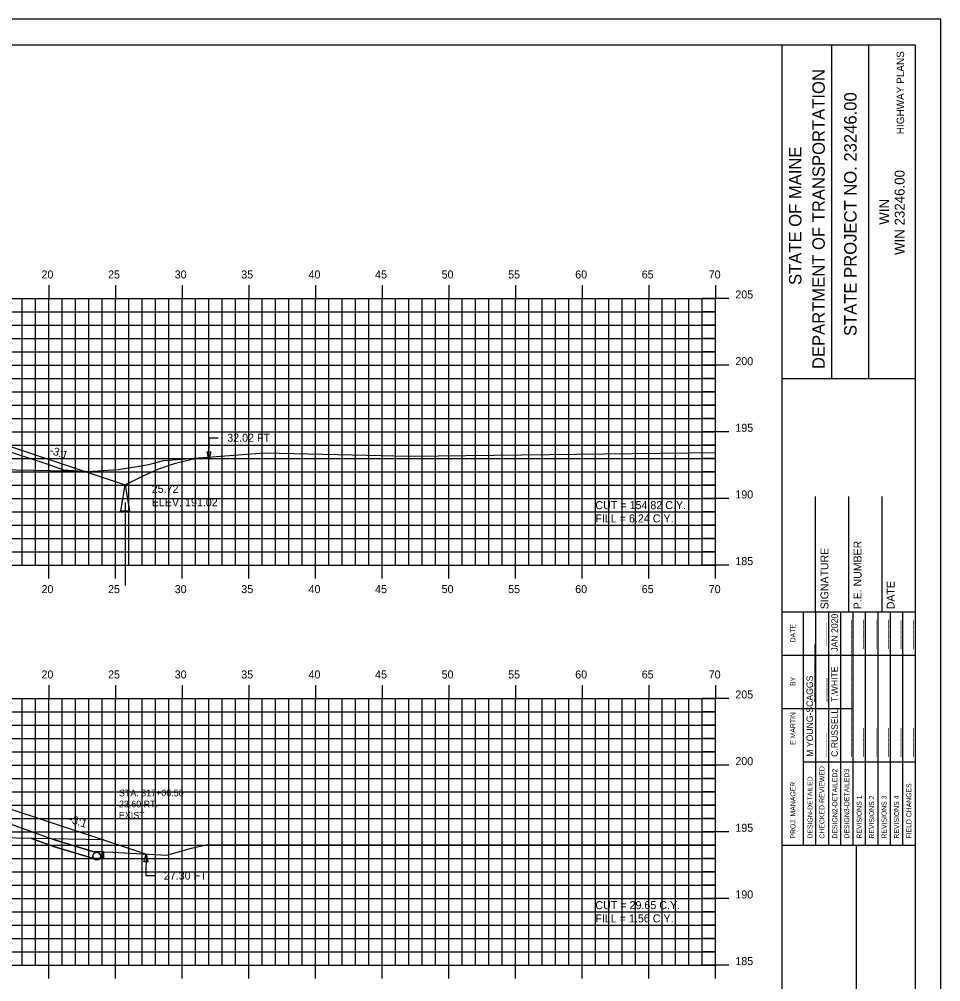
# Model space of a CAD drawing. Extents: x 1138985 to 1139155, y 608981 to 609091.
# Drawn here: x 1139085.7 to 1139154.9, y 609019.1 to 609091.3 of the extents above; entities that cross this region are included whole.
import ezdxf

# ---------------------------------------------------------------- set-up
doc = ezdxf.new("R2010")
doc.units = 0
for name, color, linetype in [('ANNOTATION', 7, 'Continuous'), ('BORDER', 7, 'Continuous'), ('D_Drainage_Ditch_Line', 7, 'Continuous'), ('D_Roadway_SlopeLines', 7, 'Continuous'), ('D_Roadway_SubGrade', 7, 'Continuous'), ('D_Text_Monospaced', 7, 'Continuous'), ('D_Text_Standard', 7, 'Continuous'), ('H_V ANNOTATION', 7, 'Continuous'), ('HIGHWAY_TITLE', 7, 'Continuous'), ('MAJOR', 7, 'Continuous'), ('MINOR', 7, 'Continuous'), ('PLOT BOUNDARY', 7, 'Continuous'), ('S_Drainage_Invert', 7, 'Continuous'), ('S_Roadway_Centerline', 7, 'Continuous'), ('SHADING', 7, 'Continuous')]:
    doc.layers.add(name, color=color, linetype=linetype)

msp = doc.modelspace()

# ---------------------------------------------------------------- linework, layer by layer
for points in [[(1139032.911, 609059.91), (1139051.198, 609059.859), (1139051.199, 609059.859), (1139051.403, 609060.487), (1139051.699, 609060.499), (1139051.949, 609059.889), (1139056.949, 609060.089), (1139067.949, 609060.309), (1139078.949, 609060.089), (1139082.949, 609059.929), (1139090.672, 609057.354), (1139093.672, 609056.354), (1139094.967, 609057.001), (1139096.217, 609057.56), (1139097.467, 609057.986), (1139098.717, 609058.28), (1139099.967, 609058.441)], [(1139037.654, 609031.141), (1139051.949, 609032.284), (1139056.949, 609032.484), (1139067.949, 609032.704), (1139078.949, 609032.484), (1139084.428, 609032.265), (1139092.057, 609029.722), (1139095.057, 609028.722), (1139095.244, 609028.66)]]:
    msp.add_lwpolyline(points)
at = {"layer": 'BORDER'}
for p, q in [((1139142.949, 608984.335), (1139142.949, 609089.335)), ((1139146.677, 609064.332), (1139146.677, 609089.332)), ((1139149.473, 609064.332), (1139149.473, 609089.332)), ((1139142.95, 609064.329), (1139152.949, 609064.329)), ((1139145.449, 609046.838), (1139145.449, 609055.485)), ((1139147.949, 609046.838), (1139147.949, 609055.485)), ((1139150.449, 609046.838), (1139150.449, 609055.485)), ((1139142.949, 609046.838), (1139152.949, 609046.838)), ((1139142.949, 609029.338), (1139152.949, 609029.338)), ((1139148.54, 608994.338), (1139148.54, 609029.338))]:
    msp.add_line(p, q, dxfattribs=at)
msp.add_lwpolyline([(1138992.949, 608984.335), (1139152.949, 608984.335), (1139152.949, 609089.335), (1138992.949, 609089.335)], close=True, dxfattribs=at)
for points in [[(1139144.564, 609043.588), (1139144.564, 609046.838)], [(1139145.496, 609029.341), (1139145.496, 609046.838)], [(1139146.428, 609046.838), (1139146.428, 609029.341)], [(1139147.36, 609029.341), (1139147.36, 609046.838)], [(1139148.291, 609029.341), (1139148.291, 609046.838)], [(1139149.223, 609029.341), (1139149.223, 609046.838)], [(1139150.155, 609029.341), (1139150.155, 609046.838)], [(1139151.086, 609029.341), (1139151.086, 609046.838)], [(1139152.018, 609029.341), (1139152.018, 609046.838)], [(1139144.565, 609029.341), (1139144.565, 609046.132)], [(1139142.949, 609043.588), (1139152.949, 609043.588)], [(1139142.949, 609039.588), (1139144.565, 609039.588)], [(1139144.564, 609039.588), (1139148.29, 609039.588)], [(1139144.564, 609035.588), (1139152.949, 609035.588)]]:
    msp.add_lwpolyline(points, dxfattribs=at)
at = {"layer": 'D_Drainage_Ditch_Line'}
msp.add_line((1139093.672, 609055.042), (1139093.672, 609048.798), dxfattribs=at)
msp.add_lwpolyline([(1139094, 609054.386), (1139093.344, 609054.386), (1139093.672, 609056.354)], close=True, dxfattribs=at)
at = {"layer": 'D_Roadway_SlopeLines'}
for points in [[(1139093.672, 609056.354), (1139094.967, 609057.001), (1139096.217, 609057.56), (1139097.467, 609057.986), (1139098.717, 609058.28), (1139099.967, 609058.441)], [(1139090.672, 609057.354), (1139093.672, 609056.354)], [(1139092.057, 609028.828), (1139092.057, 609028.328), (1139091.238, 609028.362), (1139088.304, 609029.233), (1139086.66, 609029.83)], [(1139092.057, 609029.722), (1139095.057, 609028.722)], [(1139095.057, 609028.722), (1139095.244, 609028.66)]]:
    msp.add_lwpolyline(points, dxfattribs=at)
at = {"layer": 'D_Roadway_SubGrade'}
for points in [[(1139078.949, 609059.672), (1139078.949, 609059.839), (1139082.949, 609059.679), (1139082.949, 609059.929), (1139082.949, 609059.929), (1139090.672, 609057.354), (1139078.949, 609057.589)], [(1139078.949, 609032.068), (1139078.949, 609032.234), (1139084.428, 609032.015), (1139084.428, 609032.265), (1139084.428, 609032.265), (1139092.057, 609029.722), (1139078.949, 609029.984)]]:
    msp.add_lwpolyline(points, close=True, dxfattribs=at)
at = {"layer": 'D_Text_Standard'}
for points in [[(1139099.967, 609058.251), (1139099.974, 609059.889), (1139100.654, 609059.889)], [(1139095.244, 609028.66), (1139095.22, 609027.049), (1139095.9, 609027.049)]]:
    msp.add_lwpolyline(points, dxfattribs=at)
for points in [[(1139099.967, 609058.251), (1139099.824, 609058.834), (1139100.115, 609058.833)], [(1139095.244, 609028.66), (1139095.381, 609028.076), (1139095.09, 609028.08)]]:
    msp.add_lwpolyline(points, close=True, dxfattribs=at)
at = {"layer": 'MAJOR'}
for p, q in [((1139087.949, 609071.337), (1139087.949, 609070.335)), ((1139092.949, 609071.337), (1139092.949, 609070.335)), ((1139097.949, 609071.337), (1139097.949, 609070.335)), ((1139102.949, 609071.337), (1139102.949, 609070.335)), ((1139107.949, 609071.337), (1139107.949, 609070.335)), ((1139112.949, 609071.337), (1139112.949, 609070.335)), ((1139117.949, 609071.337), (1139117.949, 609070.335)), ((1139122.949, 609071.337), (1139122.949, 609070.335)), ((1139127.949, 609071.337), (1139127.949, 609070.335)), ((1139132.949, 609071.337), (1139132.949, 609070.335)), ((1139137.949, 609071.337), (1139137.949, 609070.335)), ((1138997.949, 609070.335), (1139137.949, 609070.335)), ((1138997.949, 609070.335), (1139137.949, 609070.335)), ((1139087.949, 609050.335), (1139087.949, 609070.335)), ((1139092.949, 609050.335), (1139092.949, 609070.335)), ((1139097.949, 609050.335), (1139097.949, 609070.335)), ((1139102.949, 609050.335), (1139102.949, 609070.335)), ((1139107.949, 609050.335), (1139107.949, 609070.335)), ((1139112.949, 609050.335), (1139112.949, 609070.335)), ((1139117.949, 609050.335), (1139117.949, 609070.335)), ((1139122.949, 609050.335), (1139122.949, 609070.335)), ((1139127.949, 609050.335), (1139127.949, 609070.335)), ((1139132.949, 609050.335), (1139132.949, 609070.335)), ((1139138.951, 609070.335), (1139136.947, 609070.335)), ((1139137.949, 609050.335), (1139137.949, 609070.335)), ((1139137.949, 609050.335), (1139137.949, 609070.335)), ((1138997.949, 609065.335), (1139137.949, 609065.335)), ((1139138.951, 609065.335), (1139136.947, 609065.335)), ((1138997.949, 609060.335), (1139137.949, 609060.335)), ((1139138.951, 609060.335), (1139136.947, 609060.335)), ((1138997.949, 609055.335), (1139137.949, 609055.335)), ((1139138.951, 609055.335), (1139136.947, 609055.335)), ((1138997.949, 609050.335), (1139137.949, 609050.335)), ((1138997.949, 609050.335), (1139137.949, 609050.335)), ((1139087.949, 609049.333), (1139087.949, 609050.335)), ((1139092.949, 609049.333), (1139092.949, 609050.335)), ((1139097.949, 609049.333), (1139097.949, 609050.335)), ((1139102.949, 609049.333), (1139102.949, 609050.335)), ((1139107.949, 609049.333), (1139107.949, 609050.335)), ((1139112.949, 609049.333), (1139112.949, 609050.335)), ((1139117.949, 609049.333), (1139117.949, 609050.335)), ((1139122.949, 609049.333), (1139122.949, 609050.335)), ((1139127.949, 609049.333), (1139127.949, 609050.335)), ((1139132.949, 609049.333), (1139132.949, 609050.335)), ((1139138.951, 609050.335), (1139136.947, 609050.335)), ((1139137.949, 609049.333), (1139137.949, 609050.335)), ((1139087.949, 609041.337), (1139087.949, 609040.335)), ((1139092.949, 609041.337), (1139092.949, 609040.335)), ((1139097.949, 609041.337), (1139097.949, 609040.335)), ((1139102.949, 609041.337), (1139102.949, 609040.335)), ((1139107.949, 609041.337), (1139107.949, 609040.335)), ((1139112.949, 609041.337), (1139112.949, 609040.335)), ((1139117.949, 609041.337), (1139117.949, 609040.335)), ((1139122.949, 609041.337), (1139122.949, 609040.335)), ((1139127.949, 609041.337), (1139127.949, 609040.335)), ((1139132.949, 609041.337), (1139132.949, 609040.335)), ((1139137.949, 609041.337), (1139137.949, 609040.335)), ((1138997.949, 609040.335), (1139137.949, 609040.335)), ((1138997.949, 609040.335), (1139137.949, 609040.335)), ((1139087.949, 609020.335), (1139087.949, 609040.335)), ((1139092.949, 609020.335), (1139092.949, 609040.335)), ((1139097.949, 609020.335), (1139097.949, 609040.335)), ((1139102.949, 609020.335), (1139102.949, 609040.335)), ((1139107.949, 609020.335), (1139107.949, 609040.335)), ((1139112.949, 609020.335), (1139112.949, 609040.335)), ((1139117.949, 609020.335), (1139117.949, 609040.335)), ((1139122.949, 609020.335), (1139122.949, 609040.335)), ((1139127.949, 609020.335), (1139127.949, 609040.335)), ((1139132.949, 609020.335), (1139132.949, 609040.335)), ((1139138.951, 609040.335), (1139136.947, 609040.335)), ((1139137.949, 609020.335), (1139137.949, 609040.335)), ((1139137.949, 609020.335), (1139137.949, 609040.335)), ((1138997.949, 609035.335), (1139137.949, 609035.335)), ((1139138.951, 609035.335), (1139136.947, 609035.335)), ((1138997.949, 609030.335), (1139137.949, 609030.335)), ((1139138.951, 609030.335), (1139136.947, 609030.335)), ((1138997.949, 609025.335), (1139137.949, 609025.335)), ((1139138.951, 609025.335), (1139136.947, 609025.335)), ((1138997.949, 609020.335), (1139137.949, 609020.335)), ((1138997.949, 609020.335), (1139137.949, 609020.335)), ((1139087.949, 609019.333), (1139087.949, 609020.335)), ((1139092.949, 609019.333), (1139092.949, 609020.335)), ((1139097.949, 609019.333), (1139097.949, 609020.335)), ((1139102.949, 609019.333), (1139102.949, 609020.335)), ((1139107.949, 609019.333), (1139107.949, 609020.335)), ((1139112.949, 609019.333), (1139112.949, 609020.335)), ((1139117.949, 609019.333), (1139117.949, 609020.335)), ((1139122.949, 609019.333), (1139122.949, 609020.335)), ((1139127.949, 609019.333), (1139127.949, 609020.335)), ((1139132.949, 609019.333), (1139132.949, 609020.335)), ((1139138.951, 609020.335), (1139136.947, 609020.335)), ((1139137.949, 609019.333), (1139137.949, 609020.335))]:
    msp.add_line(p, q, dxfattribs=at)
at = {"layer": 'MINOR'}
for p, q in [((1139085.949, 609050.335), (1139085.949, 609070.335)), ((1139086.949, 609050.335), (1139086.949, 609070.335)), ((1139088.949, 609050.335), (1139088.949, 609070.335)), ((1139089.949, 609050.335), (1139089.949, 609070.335)), ((1139090.949, 609050.335), (1139090.949, 609070.335)), ((1139091.949, 609050.335), (1139091.949, 609070.335)), ((1139093.949, 609050.335), (1139093.949, 609070.335)), ((1139094.949, 609050.335), (1139094.949, 609070.335)), ((1139095.949, 609050.335), (1139095.949, 609070.335)), ((1139096.949, 609050.335), (1139096.949, 609070.335)), ((1139098.949, 609050.335), (1139098.949, 609070.335)), ((1139099.949, 609050.335), (1139099.949, 609070.335)), ((1139100.949, 609050.335), (1139100.949, 609070.335)), ((1139101.949, 609050.335), (1139101.949, 609070.335)), ((1139103.949, 609050.335), (1139103.949, 609070.335)), ((1139104.949, 609050.335), (1139104.949, 609070.335)), ((1139105.949, 609050.335), (1139105.949, 609070.335)), ((1139106.949, 609050.335), (1139106.949, 609070.335)), ((1139108.949, 609050.335), (1139108.949, 609070.335)), ((1139109.949, 609050.335), (1139109.949, 609070.335)), ((1139110.949, 609050.335), (1139110.949, 609070.335)), ((1139111.949, 609050.335), (1139111.949, 609070.335)), ((1139113.949, 609050.335), (1139113.949, 609070.335)), ((1139114.949, 609050.335), (1139114.949, 609070.335)), ((1139115.949, 609050.335), (1139115.949, 609070.335)), ((1139116.949, 609050.335), (1139116.949, 609070.335)), ((1139118.949, 609050.335), (1139118.949, 609070.335)), ((1139119.949, 609050.335), (1139119.949, 609070.335)), ((1139120.949, 609050.335), (1139120.949, 609070.335)), ((1139121.949, 609050.335), (1139121.949, 609070.335)), ((1139123.949, 609050.335), (1139123.949, 609070.335)), ((1139124.949, 609050.335), (1139124.949, 609070.335)), ((1139125.949, 609050.335), (1139125.949, 609070.335)), ((1139126.949, 609050.335), (1139126.949, 609070.335)), ((1139128.949, 609050.335), (1139128.949, 609070.335)), ((1139129.949, 609050.335), (1139129.949, 609070.335)), ((1139130.949, 609050.335), (1139130.949, 609070.335)), ((1139131.949, 609050.335), (1139131.949, 609070.335)), ((1139133.949, 609050.335), (1139133.949, 609070.335)), ((1139134.949, 609050.335), (1139134.949, 609070.335)), ((1139135.949, 609050.335), (1139135.949, 609070.335)), ((1139136.949, 609050.335), (1139136.949, 609070.335)), ((1138997.949, 609069.335), (1139137.949, 609069.335)), ((1139137.949, 609069.335), (1139136.947, 609069.335)), ((1138997.949, 609068.335), (1139137.949, 609068.335)), ((1139137.949, 609068.335), (1139136.947, 609068.335)), ((1138997.949, 609067.335), (1139137.949, 609067.335)), ((1139137.949, 609067.335), (1139136.947, 609067.335)), ((1138997.949, 609066.335), (1139137.949, 609066.335)), ((1139137.949, 609066.335), (1139136.947, 609066.335)), ((1138997.949, 609064.335), (1139137.949, 609064.335)), ((1139137.949, 609064.335), (1139136.947, 609064.335)), ((1138997.949, 609063.335), (1139137.949, 609063.335)), ((1139137.949, 609063.335), (1139136.947, 609063.335)), ((1138997.949, 609062.335), (1139137.949, 609062.335)), ((1139137.949, 609062.335), (1139136.947, 609062.335)), ((1138997.949, 609061.335), (1139137.949, 609061.335)), ((1139137.949, 609061.335), (1139136.947, 609061.335)), ((1138997.949, 609059.335), (1139137.949, 609059.335)), ((1139137.949, 609059.335), (1139136.947, 609059.335)), ((1138997.949, 609058.335), (1139137.949, 609058.335)), ((1139137.949, 609058.335), (1139136.947, 609058.335)), ((1138997.949, 609057.335), (1139137.949, 609057.335)), ((1139137.949, 609057.335), (1139136.947, 609057.335)), ((1138997.949, 609056.335), (1139137.949, 609056.335)), ((1139137.949, 609056.335), (1139136.947, 609056.335)), ((1138997.949, 609054.335), (1139137.949, 609054.335)), ((1139137.949, 609054.335), (1139136.947, 609054.335)), ((1138997.949, 609053.335), (1139137.949, 609053.335)), ((1139137.949, 609053.335), (1139136.947, 609053.335)), ((1138997.949, 609052.335), (1139137.949, 609052.335)), ((1139137.949, 609052.335), (1139136.947, 609052.335)), ((1138997.949, 609051.335), (1139137.949, 609051.335)), ((1139137.949, 609051.335), (1139136.947, 609051.335)), ((1139085.949, 609020.335), (1139085.949, 609040.335)), ((1139086.949, 609020.335), (1139086.949, 609040.335)), ((1139088.949, 609020.335), (1139088.949, 609040.335)), ((1139089.949, 609020.335), (1139089.949, 609040.335)), ((1139090.949, 609020.335), (1139090.949, 609040.335)), ((1139091.949, 609020.335), (1139091.949, 609040.335)), ((1139093.949, 609020.335), (1139093.949, 609040.335)), ((1139094.949, 609020.335), (1139094.949, 609040.335)), ((1139095.949, 609020.335), (1139095.949, 609040.335)), ((1139096.949, 609020.335), (1139096.949, 609040.335)), ((1139098.949, 609020.335), (1139098.949, 609040.335)), ((1139099.949, 609020.335), (1139099.949, 609040.335)), ((1139100.949, 609020.335), (1139100.949, 609040.335)), ((1139101.949, 609020.335), (1139101.949, 609040.335)), ((1139103.949, 609020.335), (1139103.949, 609040.335)), ((1139104.949, 609020.335), (1139104.949, 609040.335)), ((1139105.949, 609020.335), (1139105.949, 609040.335)), ((1139106.949, 609020.335), (1139106.949, 609040.335)), ((1139108.949, 609020.335), (1139108.949, 609040.335)), ((1139109.949, 609020.335), (1139109.949, 609040.335)), ((1139110.949, 609020.335), (1139110.949, 609040.335)), ((1139111.949, 609020.335), (1139111.949, 609040.335)), ((1139113.949, 609020.335), (1139113.949, 609040.335)), ((1139114.949, 609020.335), (1139114.949, 609040.335)), ((1139115.949, 609020.335), (1139115.949, 609040.335)), ((1139116.949, 609020.335), (1139116.949, 609040.335)), ((1139118.949, 609020.335), (1139118.949, 609040.335)), ((1139119.949, 609020.335), (1139119.949, 609040.335)), ((1139120.949, 609020.335), (1139120.949, 609040.335)), ((1139121.949, 609020.335), (1139121.949, 609040.335)), ((1139123.949, 609020.335), (1139123.949, 609040.335)), ((1139124.949, 609020.335), (1139124.949, 609040.335)), ((1139125.949, 609020.335), (1139125.949, 609040.335)), ((1139126.949, 609020.335), (1139126.949, 609040.335)), ((1139128.949, 609020.335), (1139128.949, 609040.335)), ((1139129.949, 609020.335), (1139129.949, 609040.335)), ((1139130.949, 609020.335), (1139130.949, 609040.335)), ((1139131.949, 609020.335), (1139131.949, 609040.335)), ((1139133.949, 609020.335), (1139133.949, 609040.335)), ((1139134.949, 609020.335), (1139134.949, 609040.335)), ((1139135.949, 609020.335), (1139135.949, 609040.335)), ((1139136.949, 609020.335), (1139136.949, 609040.335)), ((1138997.949, 609039.335), (1139137.949, 609039.335)), ((1139137.949, 609039.335), (1139136.947, 609039.335)), ((1138997.949, 609038.335), (1139137.949, 609038.335)), ((1139137.949, 609038.335), (1139136.947, 609038.335)), ((1138997.949, 609037.335), (1139137.949, 609037.335)), ((1139137.949, 609037.335), (1139136.947, 609037.335)), ((1138997.949, 609036.335), (1139137.949, 609036.335)), ((1139137.949, 609036.335), (1139136.947, 609036.335)), ((1138997.949, 609034.335), (1139137.949, 609034.335)), ((1139137.949, 609034.335), (1139136.947, 609034.335)), ((1138997.949, 609033.335), (1139137.949, 609033.335)), ((1139137.949, 609033.335), (1139136.947, 609033.335)), ((1138997.949, 609032.335), (1139137.949, 609032.335)), ((1139137.949, 609032.335), (1139136.947, 609032.335)), ((1138997.949, 609031.335), (1139137.949, 609031.335)), ((1139137.949, 609031.335), (1139136.947, 609031.335)), ((1138997.949, 609029.335), (1139137.949, 609029.335)), ((1139137.949, 609029.335), (1139136.947, 609029.335)), ((1138997.949, 609028.335), (1139137.949, 609028.335)), ((1139137.949, 609028.335), (1139136.947, 609028.335)), ((1138997.949, 609027.335), (1139137.949, 609027.335)), ((1139137.949, 609027.335), (1139136.947, 609027.335)), ((1138997.949, 609026.335), (1139137.949, 609026.335)), ((1139137.949, 609026.335), (1139136.947, 609026.335)), ((1138997.949, 609024.335), (1139137.949, 609024.335)), ((1139137.949, 609024.335), (1139136.947, 609024.335)), ((1138997.949, 609023.335), (1139137.949, 609023.335)), ((1139137.949, 609023.335), (1139136.947, 609023.335)), ((1138997.949, 609022.335), (1139137.949, 609022.335)), ((1139137.949, 609022.335), (1139136.947, 609022.335)), ((1138997.949, 609021.335), (1139137.949, 609021.335)), ((1139137.949, 609021.335), (1139136.947, 609021.335))]:
    msp.add_line(p, q, dxfattribs=at)
at = {"layer": 'PLOT BOUNDARY'}
msp.add_lwpolyline([(1138984.856, 608981.276), (1139154.856, 608981.276), (1139154.856, 609091.276), (1138984.856, 609091.276)], close=True, dxfattribs=at)
at = {"layer": 'S_Drainage_Invert'}
msp.add_circle((1139091.545, 609028.502), 0.3, dxfattribs=at)
at = {"layer": 'S_Roadway_Centerline'}
for points in [[(1139016.434, 609060.334), (1139031.885, 609059.945), (1139034.377, 609059.859), (1139052.189, 609059.505), (1139054.799, 609059.411), (1139055.727, 609059.439), (1139059.616, 609059.763), (1139066.017, 609059.781), (1139070.197, 609059.83), (1139070.369, 609060.059), (1139076.793, 609059.71), (1139080.407, 609059.613), (1139083.326, 609059.173), (1139084.343, 609059.069), (1139087.733, 609057.962), (1139089.051, 609057.481), (1139090.872, 609057.361), (1139093.183, 609057.505), (1139095.448, 609057.872), (1139096.555, 609058.182), (1139104.125, 609058.757), (1139115.082, 609058.5), (1139137.949, 609058.777)], [(1139084.628, 609031.083), (1139088.442, 609029.697), (1139091.259, 609028.861), (1139092.739, 609028.8), (1139096.816, 609028.572), (1139098.65, 609029.095), (1139099.784, 609029.348), (1139108.813, 609029.372), (1139137.949, 609029.351)]]:
    msp.add_lwpolyline(points, dxfattribs=at)
at = {"layer": 'SHADING'}
msp.add_line((1139088.159, 609029.8), (1139086.66, 609029.83), dxfattribs=at)
for points in [[(1139086.66, 609029.83), (1139088.304, 609029.233), (1139091.238, 609028.362)], [(1139092.057, 609028.828), (1139091.259, 609028.861), (1139088.442, 609029.697), (1139088.159, 609029.8)], [(1139091.238, 609028.362), (1139091.272, 609028.378)], [(1139091.797, 609028.339), (1139092.057, 609028.328), (1139092.057, 609028.828)]]:
    msp.add_lwpolyline(points, dxfattribs=at)
msp.add_arc((1139091.545, 609028.502), 0.3, 327.13179, 204.48156, dxfattribs=at)

# ---------------------------------------------------------------- texts
at = {"layer": 'ANNOTATION'}
for rotation, p in [(341.56521, (1139087.96, 609058.712)), (341.56522, (1139089.392, 609031.065))]:
    msp.add_text('-3:1', height=0.6, rotation=rotation, dxfattribs=at).set_placement(p)
at = {"layer": 'BORDER'}
for s, height, p in [('DEPARTMENT OF TRANSPORTATION', 0.93176, (1139146.156, 609065.041)), ('STATE PROJECT NO. 23246.00', 0.93176, (1139148.541, 609067.517)), ('STATE OF MAINE', 0.93176, (1139144.404, 609071.347)), ('WIN 23246.00', 0.74527, (1139152.144, 609073.596)), ('WIN', 0.7453, (1139150.986, 609075.865)), ('SIGNATURE', 0.5906, (1139146.429, 609047.03)), ('P.E. NUMBER', 0.59055, (1139148.91, 609047.03)), ('DATE', 0.5906, (1139151.39, 609047.03)), ('JAN 2020', 0.4845, (1139147.135, 609043.843)), ('DATE', 0.3714, (1139143.953, 609044.544)), ('_____', 0.4845, (1139146.166, 609044.243)), ('______', 0.4845, (1139148.03, 609044.063)), ('______', 0.4845, (1139148.961, 609044.065)), ('______', 0.4845, (1139149.893, 609044.067)), ('______', 0.4845, (1139150.825, 609044.067)), ('______', 0.4845, (1139151.756, 609044.036)), ('______', 0.4845, (1139152.688, 609044.036)), ('____________', 0.48455, (1139145.272, 609040.073)), ('____________', 0.48455, (1139148.03, 609040.073)), ('T.WHITE', 0.4845, (1139147.135, 609040.073)), ('BY', 0.3714, (1139143.953, 609041.273)), ('M YOUNG-SCAGGS', 0.48455, (1139145.272, 609035.961)), ('_____', 0.4845, (1139146.204, 609040.073)), ('____________', 0.48455, (1139148.03, 609035.961)), ('C.RUSSELL', 0.4845, (1139147.135, 609035.961)), ('E MARTIN', 0.3727, (1139143.953, 609036.855)), ('_____', 0.4845, (1139146.166, 609035.961)), ('______', 0.4845, (1139148.961, 609035.961)), ('______', 0.4845, (1139149.893, 609035.961)), ('______', 0.4845, (1139150.825, 609035.961)), ('______', 0.4845, (1139151.756, 609035.961)), ('______', 0.4845, (1139152.688, 609035.961)), ('CHECKED-REVIEWED', 0.37275, (1139146.13, 609029.826)), ('DESIGN2-DETAILED2', 0.37275, (1139147.099, 609029.826)), ('DESIGN3-DETAILED3', 0.37275, (1139147.993, 609029.826)), ('DESIGN-DETAILED', 0.37275, (1139145.235, 609029.826)), ('PROJ. MANAGER', 0.37275, (1139143.953, 609029.826)), ('FIELD CHANGES', 0.37275, (1139152.652, 609029.826)), ('REVISIONS 1', 0.37275, (1139148.925, 609029.826)), ('REVISIONS 2', 0.37275, (1139149.857, 609029.826)), ('REVISIONS 3', 0.37275, (1139150.788, 609029.826)), ('REVISIONS 4', 0.37275, (1139151.72, 609029.826))]:
    msp.add_text(s, height=height, rotation=90, dxfattribs=at).set_placement(p)
at = {"layer": 'D_Text_Monospaced'}
for s, height, p in [('STA. 317+06.50', 0.49998, (1139093.212, 609033)), ('23.60 RT.', 0.5, (1139093.212, 609032.166)), ('EXIST. ', 0.5, (1139093.212, 609031.326))]:
    msp.add_text(s, height=height, dxfattribs=at).set_placement(p)
at = {"layer": 'D_Text_Standard'}
for s, p in [('32.02 FT', (1139101.334, 609059.589)), ('25.72', (1139095.672, 609055.754)), ('ELEV. 191.02', (1139095.672, 609054.752)), ('CUT = 154.82 C.Y.', (1139128.949, 609054.535)), ('FILL = 6.24 C.Y.', (1139128.949, 609053.539)), ('27.30 FT', (1139096.58, 609026.749)), ('CUT = 29.65 C.Y.', (1139128.949, 609024.535)), ('FILL = 1.56 C.Y.', (1139128.949, 609023.539))]:
    msp.add_text(s, height=0.6, dxfattribs=at).set_placement(p)
at = {"layer": 'H_V ANNOTATION'}
for s, p in [('20', (1139087.403, 609071.835)), ('25', (1139092.395, 609071.835)), ('30', (1139097.397, 609071.835)), ('35', (1139102.389, 609071.835)), ('40', (1139107.435, 609071.835)), ('45', (1139112.427, 609071.835)), ('50', (1139117.413, 609071.835)), ('55', (1139122.405, 609071.835)), ('60', (1139127.435, 609071.835)), ('65', (1139132.427, 609071.835)), ('70', (1139137.451, 609071.835)), ('205', (1139139.449, 609070.335)), ('200', (1139139.449, 609065.335)), ('195', (1139139.449, 609060.335)), ('190', (1139139.449, 609055.335)), ('185', (1139139.449, 609050.335)), ('20', (1139087.403, 609048.235)), ('25', (1139092.395, 609048.235)), ('30', (1139097.397, 609048.235)), ('35', (1139102.389, 609048.235)), ('40', (1139107.435, 609048.235)), ('45', (1139112.427, 609048.235)), ('50', (1139117.413, 609048.235)), ('55', (1139122.405, 609048.235)), ('60', (1139127.435, 609048.235)), ('65', (1139132.427, 609048.235)), ('70', (1139137.451, 609048.235)), ('20', (1139087.403, 609041.835)), ('25', (1139092.395, 609041.835)), ('30', (1139097.397, 609041.835)), ('35', (1139102.389, 609041.835)), ('40', (1139107.435, 609041.835)), ('45', (1139112.427, 609041.835)), ('50', (1139117.413, 609041.835)), ('55', (1139122.405, 609041.835)), ('60', (1139127.435, 609041.835)), ('65', (1139132.427, 609041.835)), ('70', (1139137.451, 609041.835)), ('205', (1139139.449, 609040.335)), ('200', (1139139.449, 609035.335)), ('195', (1139139.449, 609030.335)), ('190', (1139139.449, 609025.335)), ('185', (1139139.449, 609020.335))]:
    msp.add_text(s, height=0.6, dxfattribs=at).set_placement(p)
at = {"layer": 'HIGHWAY_TITLE'}
msp.add_text('HIGHWAY PLANS', height=0.55901, rotation=90, dxfattribs=at).set_placement((1139152.107, 609082.65))

doc.saveas('drawing.dxf')
